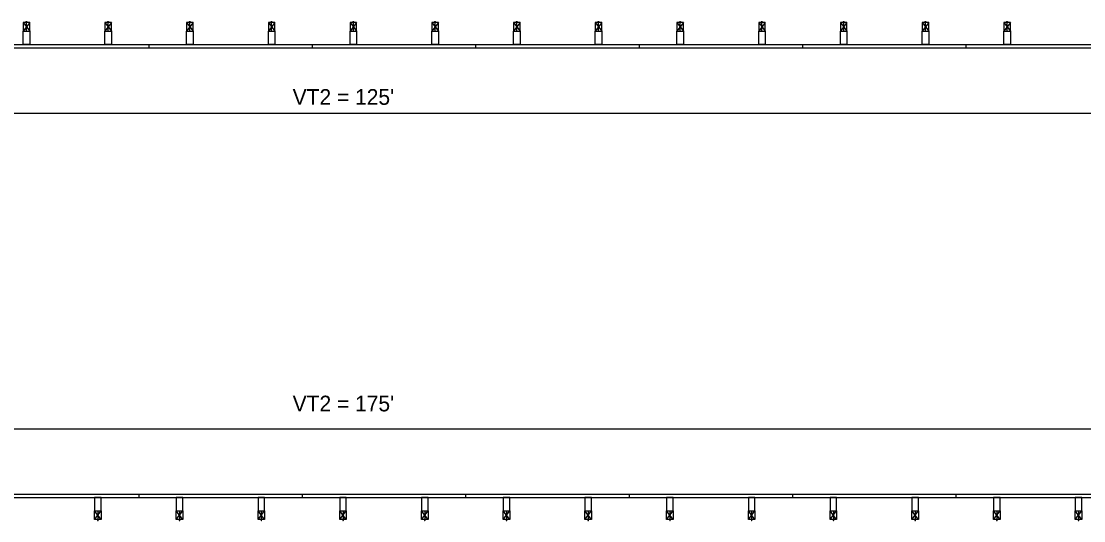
# Model space of a CAD drawing. Extents: x 16537443 to 16538473, y 7054586 to 7055469.
# Drawn here: x 16538250.1 to 16538331.4, y 7055415.8 to 7055454 of the extents above; entities that cross this region are included whole.
import ezdxf

# ---------------------------------------------------------------- set-up
doc = ezdxf.new("R2010")
doc.units = 0
doc.layers.add('Draft_DNC', color=7, linetype='Continuous')

msp = doc.modelspace()

# ---------------------------------------------------------------- linework, layer by layer
at = {"layer": 'Draft_DNC'}
for p, q in [((16538250.252, 7055453.892), (16538250.752, 7055453.225)), ((16538250.752, 7055453.892), (16538250.252, 7055453.225)), ((16538250.502, 7055453.989), (16538250.502, 7055453.996)), ((16538250.502, 7055453.225), (16538250.502, 7055453.892)), ((16538256.502, 7055453.892), (16538257.002, 7055453.225)), ((16538257.002, 7055453.892), (16538256.502, 7055453.225)), ((16538256.752, 7055453.989), (16538256.752, 7055453.996)), ((16538256.752, 7055453.225), (16538256.752, 7055453.892)), ((16538262.752, 7055453.892), (16538263.252, 7055453.225)), ((16538263.252, 7055453.892), (16538262.752, 7055453.225)), ((16538263.002, 7055453.989), (16538263.002, 7055453.996)), ((16538263.002, 7055453.225), (16538263.002, 7055453.892)), ((16538269.002, 7055453.892), (16538269.502, 7055453.225)), ((16538269.502, 7055453.892), (16538269.002, 7055453.225)), ((16538269.252, 7055453.989), (16538269.252, 7055453.996)), ((16538269.252, 7055453.225), (16538269.252, 7055453.892)), ((16538275.252, 7055453.892), (16538275.752, 7055453.225)), ((16538275.752, 7055453.892), (16538275.252, 7055453.225)), ((16538275.502, 7055453.989), (16538275.502, 7055453.996)), ((16538275.502, 7055453.225), (16538275.502, 7055453.892)), ((16538281.502, 7055453.892), (16538282.002, 7055453.225)), ((16538282.002, 7055453.892), (16538281.502, 7055453.225)), ((16538281.752, 7055453.989), (16538281.752, 7055453.996)), ((16538281.752, 7055453.225), (16538281.752, 7055453.892)), ((16538287.752, 7055453.892), (16538288.252, 7055453.225)), ((16538288.252, 7055453.892), (16538287.752, 7055453.225)), ((16538288.002, 7055453.989), (16538288.002, 7055453.996)), ((16538288.002, 7055453.225), (16538288.002, 7055453.892)), ((16538294.002, 7055453.892), (16538294.502, 7055453.225)), ((16538294.502, 7055453.892), (16538294.002, 7055453.225)), ((16538294.252, 7055453.989), (16538294.252, 7055453.996)), ((16538294.252, 7055453.225), (16538294.252, 7055453.892)), ((16538300.252, 7055453.892), (16538300.752, 7055453.225)), ((16538300.752, 7055453.892), (16538300.252, 7055453.225)), ((16538300.502, 7055453.989), (16538300.502, 7055453.996)), ((16538300.502, 7055453.225), (16538300.502, 7055453.892)), ((16538306.502, 7055453.892), (16538307.002, 7055453.225)), ((16538307.002, 7055453.892), (16538306.502, 7055453.225)), ((16538306.752, 7055453.989), (16538306.752, 7055453.996)), ((16538306.752, 7055453.225), (16538306.752, 7055453.892)), ((16538312.752, 7055453.892), (16538313.252, 7055453.225)), ((16538313.252, 7055453.892), (16538312.752, 7055453.225)), ((16538313.002, 7055453.989), (16538313.002, 7055453.996)), ((16538313.002, 7055453.225), (16538313.002, 7055453.892)), ((16538319.002, 7055453.892), (16538319.502, 7055453.225)), ((16538319.502, 7055453.892), (16538319.002, 7055453.225)), ((16538319.252, 7055453.989), (16538319.252, 7055453.996)), ((16538319.252, 7055453.225), (16538319.252, 7055453.892)), ((16538325.252, 7055453.892), (16538325.752, 7055453.225)), ((16538325.752, 7055453.892), (16538325.252, 7055453.225)), ((16538325.502, 7055453.989), (16538325.502, 7055453.996)), ((16538325.502, 7055453.225), (16538325.502, 7055453.892)), ((16538250.252, 7055453.225), (16538250.752, 7055453.225)), ((16538250.252, 7055452.225), (16538250.252, 7055453.225)), ((16538250.752, 7055453.225), (16538250.752, 7055452.225)), ((16538256.502, 7055453.225), (16538257.002, 7055453.225)), ((16538256.502, 7055452.225), (16538256.502, 7055453.225)), ((16538257.002, 7055453.225), (16538257.002, 7055452.225)), ((16538262.752, 7055453.225), (16538263.252, 7055453.225)), ((16538262.752, 7055452.225), (16538262.752, 7055453.225)), ((16538263.252, 7055453.225), (16538263.252, 7055452.225)), ((16538269.002, 7055453.225), (16538269.502, 7055453.225)), ((16538269.002, 7055452.225), (16538269.002, 7055453.225)), ((16538269.502, 7055453.225), (16538269.502, 7055452.225)), ((16538275.252, 7055453.225), (16538275.752, 7055453.225)), ((16538275.252, 7055452.225), (16538275.252, 7055453.225)), ((16538275.752, 7055453.225), (16538275.752, 7055452.225)), ((16538281.502, 7055453.225), (16538282.002, 7055453.225)), ((16538281.502, 7055452.225), (16538281.502, 7055453.225)), ((16538282.002, 7055453.225), (16538282.002, 7055452.225)), ((16538287.752, 7055453.225), (16538288.252, 7055453.225)), ((16538287.752, 7055452.225), (16538287.752, 7055453.225)), ((16538288.252, 7055453.225), (16538288.252, 7055452.225)), ((16538294.002, 7055453.225), (16538294.502, 7055453.225)), ((16538294.002, 7055452.225), (16538294.002, 7055453.225)), ((16538294.502, 7055453.225), (16538294.502, 7055452.225)), ((16538300.252, 7055453.225), (16538300.752, 7055453.225)), ((16538300.252, 7055452.225), (16538300.252, 7055453.225)), ((16538300.752, 7055453.225), (16538300.752, 7055452.225)), ((16538306.502, 7055453.225), (16538307.002, 7055453.225)), ((16538306.502, 7055452.225), (16538306.502, 7055453.225)), ((16538307.002, 7055453.225), (16538307.002, 7055452.225)), ((16538312.752, 7055453.225), (16538313.252, 7055453.225)), ((16538312.752, 7055452.225), (16538312.752, 7055453.225)), ((16538313.252, 7055453.225), (16538313.252, 7055452.225)), ((16538319.002, 7055453.225), (16538319.502, 7055453.225)), ((16538319.002, 7055452.225), (16538319.002, 7055453.225)), ((16538319.502, 7055453.225), (16538319.502, 7055452.225)), ((16538325.252, 7055453.225), (16538325.752, 7055453.225)), ((16538325.252, 7055452.225), (16538325.252, 7055453.225)), ((16538325.752, 7055453.225), (16538325.752, 7055452.225)), ((16538247.377, 7055452.225), (16538259.877, 7055452.225)), ((16538247.377, 7055451.954), (16538259.877, 7055451.954)), ((16538250.752, 7055452.225), (16538250.252, 7055452.225)), ((16538257.002, 7055452.225), (16538256.502, 7055452.225)), ((16538259.877, 7055452.225), (16538272.377, 7055452.225)), ((16538259.877, 7055451.954), (16538259.877, 7055452.225)), ((16538259.877, 7055451.954), (16538259.877, 7055452.225)), ((16538259.877, 7055451.954), (16538272.377, 7055451.954)), ((16538263.252, 7055452.225), (16538262.752, 7055452.225)), ((16538269.502, 7055452.225), (16538269.002, 7055452.225)), ((16538272.377, 7055452.225), (16538284.877, 7055452.225)), ((16538272.377, 7055451.954), (16538272.377, 7055452.225)), ((16538272.377, 7055451.954), (16538272.377, 7055452.225)), ((16538272.377, 7055451.954), (16538284.877, 7055451.954)), ((16538275.752, 7055452.225), (16538275.252, 7055452.225)), ((16538282.002, 7055452.225), (16538281.502, 7055452.225)), ((16538284.877, 7055452.225), (16538297.377, 7055452.225)), ((16538284.877, 7055451.954), (16538284.877, 7055452.225)), ((16538284.877, 7055451.954), (16538284.877, 7055452.225)), ((16538284.877, 7055451.954), (16538297.377, 7055451.954)), ((16538288.252, 7055452.225), (16538287.752, 7055452.225)), ((16538294.502, 7055452.225), (16538294.002, 7055452.225)), ((16538297.377, 7055452.225), (16538309.877, 7055452.225)), ((16538297.377, 7055451.954), (16538297.377, 7055452.225)), ((16538297.377, 7055451.954), (16538297.377, 7055452.225)), ((16538297.377, 7055451.954), (16538309.877, 7055451.954)), ((16538300.752, 7055452.225), (16538300.252, 7055452.225)), ((16538307.002, 7055452.225), (16538306.502, 7055452.225)), ((16538309.877, 7055452.225), (16538322.377, 7055452.225)), ((16538309.877, 7055451.954), (16538309.877, 7055452.225)), ((16538309.877, 7055451.954), (16538309.877, 7055452.225)), ((16538309.877, 7055451.954), (16538322.377, 7055451.954)), ((16538313.252, 7055452.225), (16538312.752, 7055452.225)), ((16538319.502, 7055452.225), (16538319.002, 7055452.225)), ((16538322.377, 7055452.225), (16538334.877, 7055452.225)), ((16538322.377, 7055451.954), (16538322.377, 7055452.225)), ((16538322.377, 7055451.954), (16538322.377, 7055452.225)), ((16538322.377, 7055451.954), (16538334.877, 7055451.954)), ((16538325.752, 7055452.225), (16538325.252, 7055452.225)), ((16538225.502, 7055446.955), (16538350.502, 7055446.957)), ((16538224.712, 7055422.833), (16538399.712, 7055422.833)), ((16538246.587, 7055417.832), (16538259.087, 7055417.832)), ((16538259.087, 7055417.832), (16538259.087, 7055417.561)), ((16538259.087, 7055417.832), (16538271.587, 7055417.832)), ((16538259.087, 7055417.832), (16538259.087, 7055417.561)), ((16538271.587, 7055417.832), (16538271.587, 7055417.561)), ((16538271.587, 7055417.832), (16538284.087, 7055417.832)), ((16538271.587, 7055417.832), (16538271.587, 7055417.561)), ((16538284.087, 7055417.832), (16538284.087, 7055417.561)), ((16538284.087, 7055417.832), (16538296.587, 7055417.832)), ((16538284.087, 7055417.832), (16538284.087, 7055417.561)), ((16538296.587, 7055417.832), (16538296.587, 7055417.561)), ((16538296.587, 7055417.832), (16538309.087, 7055417.832)), ((16538296.587, 7055417.832), (16538296.587, 7055417.561)), ((16538309.087, 7055417.832), (16538309.087, 7055417.561)), ((16538309.087, 7055417.832), (16538321.587, 7055417.832)), ((16538309.087, 7055417.832), (16538309.087, 7055417.561)), ((16538321.587, 7055417.832), (16538321.587, 7055417.561)), ((16538321.587, 7055417.832), (16538334.087, 7055417.832)), ((16538321.587, 7055417.832), (16538321.587, 7055417.561)), ((16538246.587, 7055417.561), (16538259.087, 7055417.561)), ((16538256.212, 7055417.561), (16538255.712, 7055417.561)), ((16538255.712, 7055417.561), (16538255.712, 7055416.561)), ((16538256.212, 7055416.561), (16538256.212, 7055417.561)), ((16538259.087, 7055417.561), (16538271.587, 7055417.561)), ((16538262.462, 7055417.561), (16538261.962, 7055417.561)), ((16538261.962, 7055417.561), (16538261.962, 7055416.561)), ((16538262.462, 7055416.561), (16538262.462, 7055417.561)), ((16538268.712, 7055417.561), (16538268.212, 7055417.561)), ((16538268.212, 7055417.561), (16538268.212, 7055416.561)), ((16538268.712, 7055416.561), (16538268.712, 7055417.561)), ((16538271.587, 7055417.561), (16538284.087, 7055417.561)), ((16538274.962, 7055417.561), (16538274.462, 7055417.561)), ((16538274.462, 7055417.561), (16538274.462, 7055416.561)), ((16538274.962, 7055416.561), (16538274.962, 7055417.561)), ((16538281.212, 7055417.561), (16538280.712, 7055417.561)), ((16538280.712, 7055417.561), (16538280.712, 7055416.561)), ((16538281.212, 7055416.561), (16538281.212, 7055417.561)), ((16538284.087, 7055417.561), (16538296.587, 7055417.561)), ((16538287.462, 7055417.561), (16538286.962, 7055417.561)), ((16538286.962, 7055417.561), (16538286.962, 7055416.561)), ((16538287.462, 7055416.561), (16538287.462, 7055417.561)), ((16538293.712, 7055417.561), (16538293.212, 7055417.561)), ((16538293.212, 7055417.561), (16538293.212, 7055416.561)), ((16538293.712, 7055416.561), (16538293.712, 7055417.561)), ((16538296.587, 7055417.561), (16538309.087, 7055417.561)), ((16538299.962, 7055417.561), (16538299.462, 7055417.561)), ((16538299.462, 7055417.561), (16538299.462, 7055416.561)), ((16538299.962, 7055416.561), (16538299.962, 7055417.561)), ((16538306.212, 7055417.561), (16538305.712, 7055417.561)), ((16538305.712, 7055417.561), (16538305.712, 7055416.561)), ((16538306.212, 7055416.561), (16538306.212, 7055417.561)), ((16538309.087, 7055417.561), (16538321.587, 7055417.561)), ((16538312.462, 7055417.561), (16538311.962, 7055417.561)), ((16538311.962, 7055417.561), (16538311.962, 7055416.561)), ((16538312.462, 7055416.561), (16538312.462, 7055417.561)), ((16538318.712, 7055417.561), (16538318.212, 7055417.561)), ((16538318.212, 7055417.561), (16538318.212, 7055416.561)), ((16538318.712, 7055416.561), (16538318.712, 7055417.561)), ((16538321.587, 7055417.561), (16538334.087, 7055417.561)), ((16538324.962, 7055417.561), (16538324.462, 7055417.561)), ((16538324.462, 7055417.561), (16538324.462, 7055416.561)), ((16538324.962, 7055416.561), (16538324.962, 7055417.561)), ((16538331.212, 7055417.561), (16538330.712, 7055417.561)), ((16538330.712, 7055417.561), (16538330.712, 7055416.561)), ((16538331.212, 7055416.561), (16538331.212, 7055417.561)), ((16538255.712, 7055416.561), (16538256.212, 7055416.561)), ((16538255.712, 7055415.894), (16538256.212, 7055416.561)), ((16538256.212, 7055415.894), (16538255.712, 7055416.561)), ((16538255.962, 7055416.561), (16538255.962, 7055415.894)), ((16538261.962, 7055416.561), (16538262.462, 7055416.561)), ((16538261.962, 7055415.894), (16538262.462, 7055416.561)), ((16538262.462, 7055415.894), (16538261.962, 7055416.561)), ((16538262.212, 7055416.561), (16538262.212, 7055415.894)), ((16538268.212, 7055416.561), (16538268.712, 7055416.561)), ((16538268.212, 7055415.894), (16538268.712, 7055416.561)), ((16538268.712, 7055415.894), (16538268.212, 7055416.561)), ((16538268.462, 7055416.561), (16538268.462, 7055415.894)), ((16538274.462, 7055416.561), (16538274.962, 7055416.561)), ((16538274.462, 7055415.894), (16538274.962, 7055416.561)), ((16538274.962, 7055415.894), (16538274.462, 7055416.561)), ((16538274.712, 7055416.561), (16538274.712, 7055415.894)), ((16538280.712, 7055416.561), (16538281.212, 7055416.561)), ((16538280.712, 7055415.894), (16538281.212, 7055416.561)), ((16538281.212, 7055415.894), (16538280.712, 7055416.561)), ((16538280.962, 7055416.561), (16538280.962, 7055415.894)), ((16538286.962, 7055416.561), (16538287.462, 7055416.561)), ((16538286.962, 7055415.894), (16538287.462, 7055416.561)), ((16538287.462, 7055415.894), (16538286.962, 7055416.561)), ((16538287.212, 7055416.561), (16538287.212, 7055415.894)), ((16538293.212, 7055416.561), (16538293.712, 7055416.561)), ((16538293.212, 7055415.894), (16538293.712, 7055416.561)), ((16538293.712, 7055415.894), (16538293.212, 7055416.561)), ((16538293.462, 7055416.561), (16538293.462, 7055415.894)), ((16538299.462, 7055416.561), (16538299.962, 7055416.561)), ((16538299.462, 7055415.894), (16538299.962, 7055416.561)), ((16538299.962, 7055415.894), (16538299.462, 7055416.561)), ((16538299.712, 7055416.561), (16538299.712, 7055415.894)), ((16538305.712, 7055416.561), (16538306.212, 7055416.561)), ((16538305.712, 7055415.894), (16538306.212, 7055416.561)), ((16538306.212, 7055415.894), (16538305.712, 7055416.561)), ((16538305.962, 7055416.561), (16538305.962, 7055415.894)), ((16538311.962, 7055416.561), (16538312.462, 7055416.561)), ((16538311.962, 7055415.894), (16538312.462, 7055416.561)), ((16538312.462, 7055415.894), (16538311.962, 7055416.561)), ((16538312.212, 7055416.561), (16538312.212, 7055415.894)), ((16538318.212, 7055416.561), (16538318.712, 7055416.561)), ((16538318.212, 7055415.894), (16538318.712, 7055416.561)), ((16538318.712, 7055415.894), (16538318.212, 7055416.561)), ((16538318.462, 7055416.561), (16538318.462, 7055415.894)), ((16538324.462, 7055416.561), (16538324.962, 7055416.561)), ((16538324.462, 7055415.894), (16538324.962, 7055416.561)), ((16538324.962, 7055415.894), (16538324.462, 7055416.561)), ((16538324.712, 7055416.561), (16538324.712, 7055415.894)), ((16538330.712, 7055416.561), (16538331.212, 7055416.561)), ((16538330.712, 7055415.894), (16538331.212, 7055416.561)), ((16538331.212, 7055415.894), (16538330.712, 7055416.561)), ((16538330.962, 7055416.561), (16538330.962, 7055415.894)), ((16538255.962, 7055415.797), (16538255.962, 7055415.79)), ((16538262.212, 7055415.797), (16538262.212, 7055415.79)), ((16538268.462, 7055415.797), (16538268.462, 7055415.79)), ((16538274.712, 7055415.797), (16538274.712, 7055415.79)), ((16538280.962, 7055415.797), (16538280.962, 7055415.79)), ((16538287.212, 7055415.797), (16538287.212, 7055415.79)), ((16538293.462, 7055415.797), (16538293.462, 7055415.79)), ((16538299.712, 7055415.797), (16538299.712, 7055415.79)), ((16538305.962, 7055415.797), (16538305.962, 7055415.79)), ((16538312.212, 7055415.797), (16538312.212, 7055415.79)), ((16538318.462, 7055415.797), (16538318.462, 7055415.79)), ((16538324.712, 7055415.797), (16538324.712, 7055415.79)), ((16538330.962, 7055415.797), (16538330.962, 7055415.79))]:
    msp.add_line(p, q, dxfattribs=at)
for points in [[(16538250.252, 7055453.225), (16538250.752, 7055453.225), (16538250.752, 7055453.892), (16538250.252, 7055453.892)], [(16538256.502, 7055453.225), (16538257.002, 7055453.225), (16538257.002, 7055453.892), (16538256.502, 7055453.892)], [(16538262.752, 7055453.225), (16538263.252, 7055453.225), (16538263.252, 7055453.892), (16538262.752, 7055453.892)], [(16538269.002, 7055453.225), (16538269.502, 7055453.225), (16538269.502, 7055453.892), (16538269.002, 7055453.892)], [(16538275.252, 7055453.225), (16538275.752, 7055453.225), (16538275.752, 7055453.892), (16538275.252, 7055453.892)], [(16538281.502, 7055453.225), (16538282.002, 7055453.225), (16538282.002, 7055453.892), (16538281.502, 7055453.892)], [(16538287.752, 7055453.225), (16538288.252, 7055453.225), (16538288.252, 7055453.892), (16538287.752, 7055453.892)], [(16538294.002, 7055453.225), (16538294.502, 7055453.225), (16538294.502, 7055453.892), (16538294.002, 7055453.892)], [(16538300.252, 7055453.225), (16538300.752, 7055453.225), (16538300.752, 7055453.892), (16538300.252, 7055453.892)], [(16538306.502, 7055453.225), (16538307.002, 7055453.225), (16538307.002, 7055453.892), (16538306.502, 7055453.892)], [(16538312.752, 7055453.225), (16538313.252, 7055453.225), (16538313.252, 7055453.892), (16538312.752, 7055453.892)], [(16538319.002, 7055453.225), (16538319.502, 7055453.225), (16538319.502, 7055453.892), (16538319.002, 7055453.892)], [(16538325.252, 7055453.225), (16538325.752, 7055453.225), (16538325.752, 7055453.892), (16538325.252, 7055453.892)], [(16538255.712, 7055416.561), (16538256.212, 7055416.561), (16538256.212, 7055415.894), (16538255.712, 7055415.894)], [(16538261.962, 7055416.561), (16538262.462, 7055416.561), (16538262.462, 7055415.894), (16538261.962, 7055415.894)], [(16538268.212, 7055416.561), (16538268.712, 7055416.561), (16538268.712, 7055415.894), (16538268.212, 7055415.894)], [(16538274.462, 7055416.561), (16538274.962, 7055416.561), (16538274.962, 7055415.894), (16538274.462, 7055415.894)], [(16538280.712, 7055416.561), (16538281.212, 7055416.561), (16538281.212, 7055415.894), (16538280.712, 7055415.894)], [(16538286.962, 7055416.561), (16538287.462, 7055416.561), (16538287.462, 7055415.894), (16538286.962, 7055415.894)], [(16538293.212, 7055416.561), (16538293.712, 7055416.561), (16538293.712, 7055415.894), (16538293.212, 7055415.894)], [(16538299.462, 7055416.561), (16538299.962, 7055416.561), (16538299.962, 7055415.894), (16538299.462, 7055415.894)], [(16538305.712, 7055416.561), (16538306.212, 7055416.561), (16538306.212, 7055415.894), (16538305.712, 7055415.894)], [(16538311.962, 7055416.561), (16538312.462, 7055416.561), (16538312.462, 7055415.894), (16538311.962, 7055415.894)], [(16538318.212, 7055416.561), (16538318.712, 7055416.561), (16538318.712, 7055415.894), (16538318.212, 7055415.894)], [(16538324.462, 7055416.561), (16538324.962, 7055416.561), (16538324.962, 7055415.894), (16538324.462, 7055415.894)], [(16538330.712, 7055416.561), (16538331.212, 7055416.561), (16538331.212, 7055415.894), (16538330.712, 7055415.894)]]:
    msp.add_lwpolyline(points, close=True, dxfattribs=at)
for points in [[(16538250.469, 7055453.892), (16538250.469, 7055453.935), (16538250.535, 7055453.935), (16538250.535, 7055453.892)], [(16538250.483, 7055453.935), (16538250.483, 7055453.989), (16538250.522, 7055453.989), (16538250.522, 7055453.935)], [(16538256.719, 7055453.892), (16538256.719, 7055453.935), (16538256.785, 7055453.935), (16538256.785, 7055453.892)], [(16538256.733, 7055453.935), (16538256.733, 7055453.989), (16538256.772, 7055453.989), (16538256.772, 7055453.935)], [(16538262.969, 7055453.892), (16538262.969, 7055453.935), (16538263.035, 7055453.935), (16538263.035, 7055453.892)], [(16538262.983, 7055453.935), (16538262.983, 7055453.989), (16538263.022, 7055453.989), (16538263.022, 7055453.935)], [(16538269.219, 7055453.892), (16538269.219, 7055453.935), (16538269.285, 7055453.935), (16538269.285, 7055453.892)], [(16538269.233, 7055453.935), (16538269.233, 7055453.989), (16538269.272, 7055453.989), (16538269.272, 7055453.935)], [(16538275.469, 7055453.892), (16538275.469, 7055453.935), (16538275.535, 7055453.935), (16538275.535, 7055453.892)], [(16538275.483, 7055453.935), (16538275.483, 7055453.989), (16538275.522, 7055453.989), (16538275.522, 7055453.935)], [(16538281.719, 7055453.892), (16538281.719, 7055453.935), (16538281.785, 7055453.935), (16538281.785, 7055453.892)], [(16538281.733, 7055453.935), (16538281.733, 7055453.989), (16538281.772, 7055453.989), (16538281.772, 7055453.935)], [(16538287.969, 7055453.892), (16538287.969, 7055453.935), (16538288.035, 7055453.935), (16538288.035, 7055453.892)], [(16538287.983, 7055453.935), (16538287.983, 7055453.989), (16538288.022, 7055453.989), (16538288.022, 7055453.935)], [(16538294.219, 7055453.892), (16538294.219, 7055453.935), (16538294.285, 7055453.935), (16538294.285, 7055453.892)], [(16538294.233, 7055453.935), (16538294.233, 7055453.989), (16538294.272, 7055453.989), (16538294.272, 7055453.935)], [(16538300.469, 7055453.892), (16538300.469, 7055453.935), (16538300.535, 7055453.935), (16538300.535, 7055453.892)], [(16538300.483, 7055453.935), (16538300.483, 7055453.989), (16538300.522, 7055453.989), (16538300.522, 7055453.935)], [(16538306.719, 7055453.892), (16538306.719, 7055453.935), (16538306.785, 7055453.935), (16538306.785, 7055453.892)], [(16538306.733, 7055453.935), (16538306.733, 7055453.989), (16538306.772, 7055453.989), (16538306.772, 7055453.935)], [(16538312.969, 7055453.892), (16538312.969, 7055453.935), (16538313.035, 7055453.935), (16538313.035, 7055453.892)], [(16538312.983, 7055453.935), (16538312.983, 7055453.989), (16538313.022, 7055453.989), (16538313.022, 7055453.935)], [(16538319.219, 7055453.892), (16538319.219, 7055453.935), (16538319.285, 7055453.935), (16538319.285, 7055453.892)], [(16538319.233, 7055453.935), (16538319.233, 7055453.989), (16538319.272, 7055453.989), (16538319.272, 7055453.935)], [(16538325.469, 7055453.892), (16538325.469, 7055453.935), (16538325.535, 7055453.935), (16538325.535, 7055453.892)], [(16538325.483, 7055453.935), (16538325.483, 7055453.989), (16538325.522, 7055453.989), (16538325.522, 7055453.935)], [(16538255.928, 7055415.894), (16538255.928, 7055415.851), (16538255.995, 7055415.851), (16538255.995, 7055415.894)], [(16538255.942, 7055415.851), (16538255.942, 7055415.797), (16538255.981, 7055415.797), (16538255.981, 7055415.851)], [(16538262.178, 7055415.894), (16538262.178, 7055415.851), (16538262.245, 7055415.851), (16538262.245, 7055415.894)], [(16538262.192, 7055415.851), (16538262.192, 7055415.797), (16538262.231, 7055415.797), (16538262.231, 7055415.851)], [(16538268.428, 7055415.894), (16538268.428, 7055415.851), (16538268.495, 7055415.851), (16538268.495, 7055415.894)], [(16538268.442, 7055415.851), (16538268.442, 7055415.797), (16538268.481, 7055415.797), (16538268.481, 7055415.851)], [(16538274.678, 7055415.894), (16538274.678, 7055415.851), (16538274.745, 7055415.851), (16538274.745, 7055415.894)], [(16538274.692, 7055415.851), (16538274.692, 7055415.797), (16538274.731, 7055415.797), (16538274.731, 7055415.851)], [(16538280.928, 7055415.894), (16538280.928, 7055415.851), (16538280.995, 7055415.851), (16538280.995, 7055415.894)], [(16538280.942, 7055415.851), (16538280.942, 7055415.797), (16538280.981, 7055415.797), (16538280.981, 7055415.851)], [(16538287.178, 7055415.894), (16538287.178, 7055415.851), (16538287.245, 7055415.851), (16538287.245, 7055415.894)], [(16538287.192, 7055415.851), (16538287.192, 7055415.797), (16538287.231, 7055415.797), (16538287.231, 7055415.851)], [(16538293.428, 7055415.894), (16538293.428, 7055415.851), (16538293.495, 7055415.851), (16538293.495, 7055415.894)], [(16538293.442, 7055415.851), (16538293.442, 7055415.797), (16538293.481, 7055415.797), (16538293.481, 7055415.851)], [(16538299.678, 7055415.894), (16538299.678, 7055415.851), (16538299.745, 7055415.851), (16538299.745, 7055415.894)], [(16538299.692, 7055415.851), (16538299.692, 7055415.797), (16538299.731, 7055415.797), (16538299.731, 7055415.851)], [(16538305.928, 7055415.894), (16538305.928, 7055415.851), (16538305.995, 7055415.851), (16538305.995, 7055415.894)], [(16538305.942, 7055415.851), (16538305.942, 7055415.797), (16538305.981, 7055415.797), (16538305.981, 7055415.851)], [(16538312.178, 7055415.894), (16538312.178, 7055415.851), (16538312.245, 7055415.851), (16538312.245, 7055415.894)], [(16538312.192, 7055415.851), (16538312.192, 7055415.797), (16538312.231, 7055415.797), (16538312.231, 7055415.851)], [(16538318.428, 7055415.894), (16538318.428, 7055415.851), (16538318.495, 7055415.851), (16538318.495, 7055415.894)], [(16538318.442, 7055415.851), (16538318.442, 7055415.797), (16538318.481, 7055415.797), (16538318.481, 7055415.851)], [(16538324.678, 7055415.894), (16538324.678, 7055415.851), (16538324.745, 7055415.851), (16538324.745, 7055415.894)], [(16538324.692, 7055415.851), (16538324.692, 7055415.797), (16538324.731, 7055415.797), (16538324.731, 7055415.851)], [(16538330.928, 7055415.894), (16538330.928, 7055415.851), (16538330.995, 7055415.851), (16538330.995, 7055415.894)], [(16538330.942, 7055415.851), (16538330.942, 7055415.797), (16538330.981, 7055415.797), (16538330.981, 7055415.851)]]:
    msp.add_lwpolyline(points, dxfattribs=at)

# ---------------------------------------------------------------- texts
for s, p in [("VT2 = 125'", (16538270.863, 7055447.605)), ("VT2 = 175'", (16538270.863, 7055424.156))]:
    msp.add_text(s, height=1.2, rotation=0.00101, dxfattribs=at).set_placement(p)

doc.saveas('drawing.dxf')
